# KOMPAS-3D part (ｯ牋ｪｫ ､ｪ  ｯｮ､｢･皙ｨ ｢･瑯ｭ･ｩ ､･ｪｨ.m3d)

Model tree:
1. Эскиз:1
2. Операция выдавливания:1
     Расстояние 1 = 3
3. Эскиз:2
4. Вырезать элемент выдавливания:1
     Толщина стенки 1 = 2; Расстояние 1 = 10
5. Эскиз:3
6. Вырезать элемент выдавливания:2
     Расстояние 1 = 50
